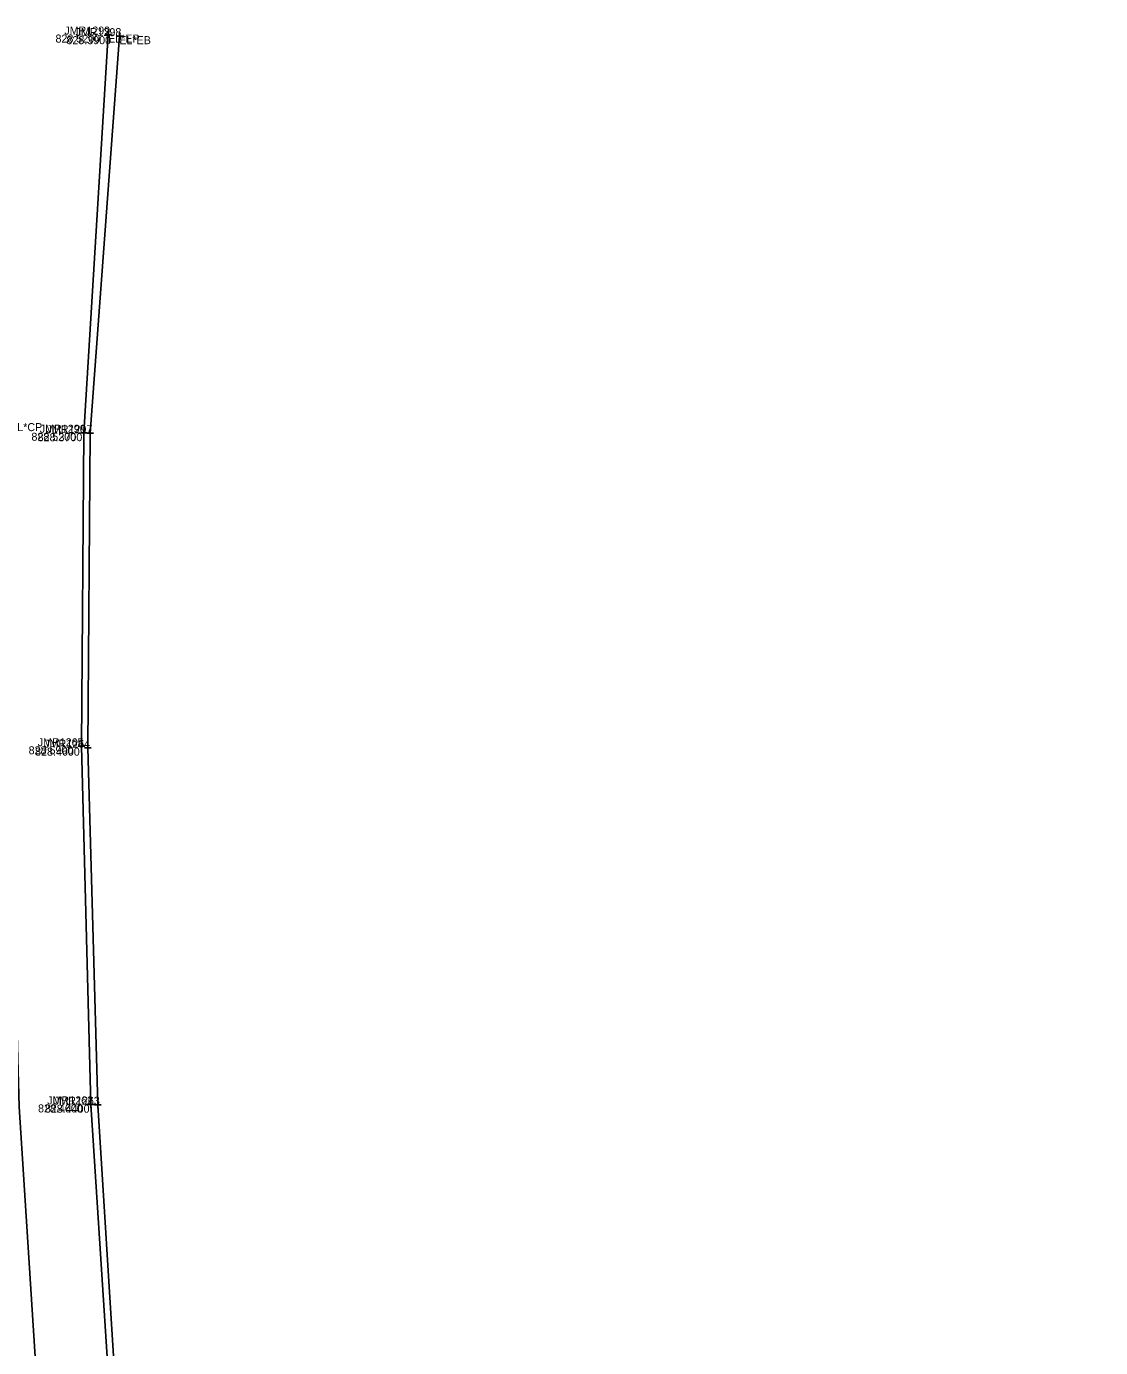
# Model space of a CAD drawing. Extents: x 1800057 to 1804439, y 483822 to 495007.
# Drawn here: x 1800169.1 to 1800330.1, y 493615 to 493813 of the extents above; entities that cross this region are included whole.
import ezdxf

# ---------------------------------------------------------------- set-up
doc = ezdxf.new("R2010")
doc.units = 0
for name, color, linetype in [('PV_X_EOP', 7, 'Continuous'), ('PV_X_Shoulder', 7, 'Continuous'), ('SV_X_Center_of_Pavt', 7, 'Continuous'), ('SV_X_Shot_Marker', 7, 'Continuous'), ('SV_X_Text_Comment', 7, 'Continuous'), ('SV_X_Text_Elevation', 7, 'Continuous'), ('SV_X_Text_Name', 7, 'Continuous')]:
    doc.layers.add(name, color=color, linetype=linetype)

msp = doc.modelspace()

# ---------------------------------------------------------------- linework, layer by layer
at = {"layer": 'PV_X_EOP'}
msp.add_lwpolyline([(1800479.55, 492023.06), (1800449.85, 492176.97), (1800392.6, 492464.18), (1800311.54, 492873.87), (1800256.42, 493152.44), (1800212.54, 493383.09), (1800204.6, 493426.98), (1800197.72, 493469.35), (1800191.09, 493515.34), (1800186.01, 493557.29), (1800181.98, 493601.37), (1800178.73, 493651.43), (1800177.31, 493705.12), (1800177.69, 493752.12), (1800181.3, 493811.81)], dxfattribs=at)
at = {"layer": 'PV_X_Shoulder'}
msp.add_lwpolyline([(1800480.74, 492023.27), (1800451.07, 492177.26), (1800394.03, 492464.67), (1800312.92, 492873.97), (1800257.77, 493152.69), (1800213.69, 493383.34), (1800205.58, 493427.28), (1800198.52, 493469.53), (1800192.09, 493515.4), (1800187.03, 493557.46), (1800182.89, 493601.49), (1800179.75, 493651.39), (1800178.29, 493704.91), (1800178.63, 493752.05), (1800182.99, 493811.57)], dxfattribs=at)
at = {"layer": 'SV_X_Center_of_Pavt'}
msp.add_lwpolyline([(1800469.01, 492021.22), (1800439.37, 492174.81), (1800382.15, 492462.11), (1800301, 492872.15), (1800245.93, 493151.03), (1800202.07, 493381.28), (1800193.97, 493425.46), (1800186.87, 493467.92), (1800180.32, 493514.37), (1800175.39, 493555.88), (1800171.19, 493600.63), (1800167.99, 493651.05), (1800166.49, 493705.44), (1800166.61, 493753.56)], dxfattribs=at)
at = {"layer": 'SV_X_Shot_Marker'}
for p, q in [((1800180.8, 493811.81), (1800181.8, 493811.81)), ((1800181.3, 493812.31), (1800181.3, 493811.31)), ((1800181.3, 493811.81), (1800181.3, 493811.81)), ((1800182.49, 493811.57), (1800183.49, 493811.57)), ((1800182.99, 493812.07), (1800182.99, 493811.07)), ((1800182.99, 493811.57), (1800182.99, 493811.57)), ((1800177.69, 493752.62), (1800177.69, 493751.62)), ((1800178.63, 493752.55), (1800178.63, 493751.55)), ((1800177.19, 493752.12), (1800178.19, 493752.12)), ((1800177.69, 493752.12), (1800177.69, 493752.12)), ((1800178.13, 493752.05), (1800179.13, 493752.05)), ((1800178.63, 493752.05), (1800178.63, 493752.05)), ((1800176.81, 493705.12), (1800177.81, 493705.12)), ((1800177.31, 493705.62), (1800177.31, 493704.62)), ((1800177.31, 493705.12), (1800177.31, 493705.12)), ((1800177.79, 493704.91), (1800178.79, 493704.91)), ((1800178.29, 493705.41), (1800178.29, 493704.41)), ((1800178.29, 493704.91), (1800178.29, 493704.91)), ((1800178.23, 493651.43), (1800179.23, 493651.43)), ((1800178.73, 493651.93), (1800178.73, 493650.93)), ((1800178.73, 493651.43), (1800178.73, 493651.43)), ((1800179.25, 493651.39), (1800180.25, 493651.39)), ((1800179.75, 493651.89), (1800179.75, 493650.89)), ((1800179.75, 493651.39), (1800179.75, 493651.39))]:
    msp.add_line(p, q, dxfattribs=at)

# ---------------------------------------------------------------- texts
at = {"layer": 'SV_X_Text_Comment'}
for s, p in [('EL*EP', (1800181.3, 493810.61)), ('EL*EB', (1800182.99, 493810.37)), ('EL*CP', (1800166.61, 493752.36))]:
    msp.add_text(s, height=1.2, dxfattribs=at).set_placement(p)
at = {"layer": 'SV_X_Text_Elevation'}
for s, p in [('828.5200', (1800173.42, 493810.61)), ('828.3900', (1800175.05, 493810.37)), ('828.5200', (1800169.81, 493750.92)), ('828.3700', (1800170.74, 493750.85)), ('828.5900', (1800169.39, 493703.92)), ('828.4600', (1800170.36, 493703.71)), ('828.4600', (1800170.8, 493650.23)), ('828.4400', (1800171.83, 493650.19))]:
    msp.add_text(s, height=1.2, dxfattribs=at).set_placement(p)
at = {"layer": 'SV_X_Text_Name'}
for s, p in [('JMR1299', (1800174.74, 493811.81)), ('JMR1298', (1800176.42, 493811.57)), ('JMR1296', (1800171.06, 493752.12)), ('JMR1297', (1800172.08, 493752.05)), ('JMR1265', (1800170.75, 493705.12)), ('JMR1264', (1800171.74, 493704.91)), ('JMR1262', (1800172.18, 493651.43)), ('JMR1263', (1800173.19, 493651.39))]:
    msp.add_text(s, height=1.2, dxfattribs=at).set_placement(p)

doc.saveas('drawing.dxf')
